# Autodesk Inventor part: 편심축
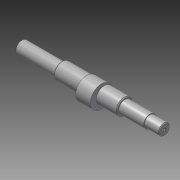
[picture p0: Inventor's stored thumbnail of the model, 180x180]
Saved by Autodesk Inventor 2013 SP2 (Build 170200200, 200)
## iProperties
Created: 2016-05
Part Number: 편심축
Document SubType Name: Modeling
Designer: mduedu
Density: 7.86 g/cm^3
Material: 강철, 연강
Author: mduedu
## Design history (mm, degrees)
sketch "스케치1"
  geometry: L1 (-42.5, 11)-(-42.5, 8.5); L2 (43.5, 11)-(43.5, 8.5); L3 (-97.5, 0)-(97.5, 0); L4 (-42.5, 11)-(43.5, 11); L5 (43.5, 11)-(43.5, 8.5); L6 (-42.5, 11)-(-42.5, 8.5); L7 (-42.5, 8.5)-(-97.5, 8.5); L8 (-97.5, 8.5)-(-97.5, 0); L9 (43.5, 8.5)-(77.5, 8.5); L10 (97.5, 7.5)-(97.5, 0); L11 (77.5, 8.5)-(77.5, 7.5); L12 (77.5, 7.5)-(97.5, 7.5); 1 further point
  constraints: 24 end point, 9 perpendicular, 2 midpoint, 1 collinear, 1 horizontal
  dimensions: "d0" = 22 diameter of L4 L3; "d1" = 17 diameter of L7 L3; "d2" = 55 distance between parallel lines of L8 L1; "d3" = 54 distance between parallel lines of L10 L2; "d4" = 15 diameter of L12 L3; "d5" = 20 distance between parallel lines of L10 L11; "d29" = 86 distance of L1.start L2.start
revolve "회전1" stored, may be unused: angle "d6" = 90 deg
node "작업 평면7"
node "작업 평면9"
sketch "스케치2"
  geometry: C1 r 11 at (0, 0); C2 r 15 at (0, -4); C3 r 11 at (0, 0); 2 further points
  constraints: 3 centre point, 2 coincident, 1 concentric, 1 vertical alignment
  dimensions: "d9" = 4 distance of point (0, 0) C2.centre; "d10" = 30 diameter of C2
extrude "돌출1" join sketch "스케치2" stored distance "d11" = 20; taper "d12" = 0 deg
chamfer "모따기1" distance "d17" = 1; stored, may be unused: second distance "d18" = 2, angle "d19" = 45 deg
node "작업 평면4"
sketch "스케치4"
  geometry: L1 (-10, -6.5)-(-10, 6.5) reference; L2 (-5, 2.5)-(5, 2.5); L3 (5, -2.5)-(-5, -2.5); A1 r 2.5 centre (5, 0) between (5, -2.5) and (5, 2.5); A2 r 2.5 centre (-5, 0) between (-5, 2.5) and (-5, -2.5); 2 further points
  constraints: 4 end point, 4 point on circle, 4 tangent, 2 centre point, 1 horizontal alignment, 1 midpoint, 1 parallel, 1 perpendicular
  dimensions: "d20" = 5 distance between parallel lines of L3 L2; "d21" = 15 dimension on A1 A2; "d22" = 2.5 distance edge to line of A2 L1
extrude "돌출3" cut sketch "스케치4" distance "d23" = 3; taper "d24" = 0 deg
node "작업 평면5"
sketch "스케치5"
  geometry: L1 (27.5, 7.5)-(27.5, -7.5) reference; L2 (27.5, 2.5)-(10, 2.5); L3 (10, -2.5)-(27.5, -2.5); A1 r 2.5 centre (10, 0) between (10, 2.5) and (10, -2.5); 2 further points
  constraints: 4 end point, 2 perpendicular, 2 point on circle, 2 point on line, 2 tangent, 1 centre point, 1 horizontal alignment, 1 midpoint
  dimensions: "d25" = 5 distance between parallel lines of L3 L2; "d26" = 20 dimension on A1 L1
extrude "돌출4" cut sketch "스케치5" distance "d27" = 3; taper "d28" = 0 deg
hole "구멍1" diameter "d34" = 3.242; stored, may be unused: countersink angle "d38" = 90 deg, drill point angle "d40" = 118 deg; dims "d35" = 9, "d36" = 4, "d37" = 2, "d39" = 11, "d43" = 10, "d44" = 10
node "솔리드1"
other parameters: "d31" = -38
